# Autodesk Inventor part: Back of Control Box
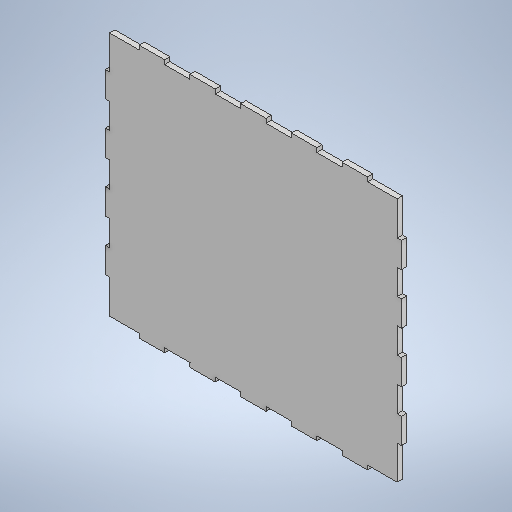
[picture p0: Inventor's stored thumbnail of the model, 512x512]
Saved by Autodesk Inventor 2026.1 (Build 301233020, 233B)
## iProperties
Created: 2026-11
Part Number: Back of Control Box
Material: Generic
Document SubType Name: Modeling
Designer: hp
Density: 1 g/cm^3
Appearance: Default
Author: hp
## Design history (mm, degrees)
sketch "Sketch1"
  geometry: L1 (0, 240)-(280, 240); L2 (280, 240)-(280, 0); L3 (280, 0)-(0, 0); L4 (0, 0)-(0, 240); L5 (152, 0)-(128, 0); L6 (128, 0)-(128, 4); L7 (128, 4)-(152, 4); L8 (152, 4)-(152, 0); L9 (104, 0)-(80, 0); L10 (80, 0)-(80, 4); L11 (80, 4)-(104, 4); L12 (104, 4)-(104, 0); L13 (56, 0)-(32, 0); L14 (32, 0)-(32, 4); L15 (32, 4)-(56, 4); L16 (56, 4)-(56, 0); L17 (200, 0)-(176, 0); L18 (176, 0)-(176, 4); L19 (176, 4)-(200, 4); L20 (200, 4)-(200, 0); L21 (152, 0)-(128, 0); L22 (128, 0)-(128, 4); L23 (128, 4)-(152, 4); L24 (152, 4)-(152, 0); L25 (104, 0)-(80, 0); L26 (80, 0)-(80, 4); L27 (80, 4)-(104, 4); L28 (104, 4)-(104, 0); L29 (248, 0)-(224, 0); L30 (224, 0)-(224, 4); L31 (224, 4)-(248, 4); L32 (248, 4)-(248, 0); L33 (200, 0)-(176, 0); L34 (176, 0)-(176, 4); L35 (176, 4)-(200, 4); L36 (200, 4)-(200, 0); L37 (152, 0)-(128, 0); L38 (128, 0)-(128, 4); L39 (128, 4)-(152, 4); L40 (152, 4)-(152, 0); L41 (280, 120)-(0, 120); L42 (140, 240)-(140, 0); L43 (200, 236)-(200, 240); L44 (200, 240)-(176, 240); L45 (176, 240)-(176, 236); L46 (176, 236)-(200, 236); L47 (152, 236)-(152, 240); L48 (152, 240)-(128, 240); L49 (128, 240)-(128, 236); L50 (128, 236)-(152, 236); L51 (56, 236)-(56, 240); L52 (80, 240)-(80, 236); L53 (80, 236)-(104, 236); L54 (104, 240)-(80, 240); L55 (104, 236)-(104, 240); L56 (56, 240)-(32, 240); L57 (32, 240)-(32, 236); L58 (32, 236)-(56, 236); L59 (224, 236)-(248, 236); L60 (248, 236)-(248, 240); L61 (248, 240)-(224, 240); L62 (224, 240)-(224, 236); L63 (152, 236)-(152, 240); L64 (200, 240)-(176, 240)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; 153 further points
  constraints: 308 end point, 90 symmetric about line, 8 parallel, 6 midpoint, 5 horizontal, 4 perpendicular, 2 vertical, 1 point on line, 3 other
  dimensions: "d8" = 280 distance of L2.end L3.end; "d9" = 240 distance of L1.end L2.end; "d10" = 24 distance of L6.end L7.end; "d11" = 4 distance of L5.end L6.end; "d12" = 48 distance of L5.start L9.start; "d13" = 48 distance of L5.start L17.start; "d14" = 4 distance of L81.end L80.end; "d15" = 24 distance of L80.end L79.end; "d16" = 48 distance of L79.end L83.end; "d17" = 48 distance of L79.end L91.end; "d18" = 4 distance between parallel lines of L1 L151
extrude "Extrusion1" new body sketch "Sketch1" distance "d19" = 5; taper "d20" = 0 deg
body "Solid1"
node "Sketch Rectangular Pattern2" dims "d12" = 48, "d13" = 48
node "Sketch Rectangular Pattern4" dims "d16" = 48, "d17" = 48
